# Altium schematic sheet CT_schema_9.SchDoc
size 254 x 194 mm
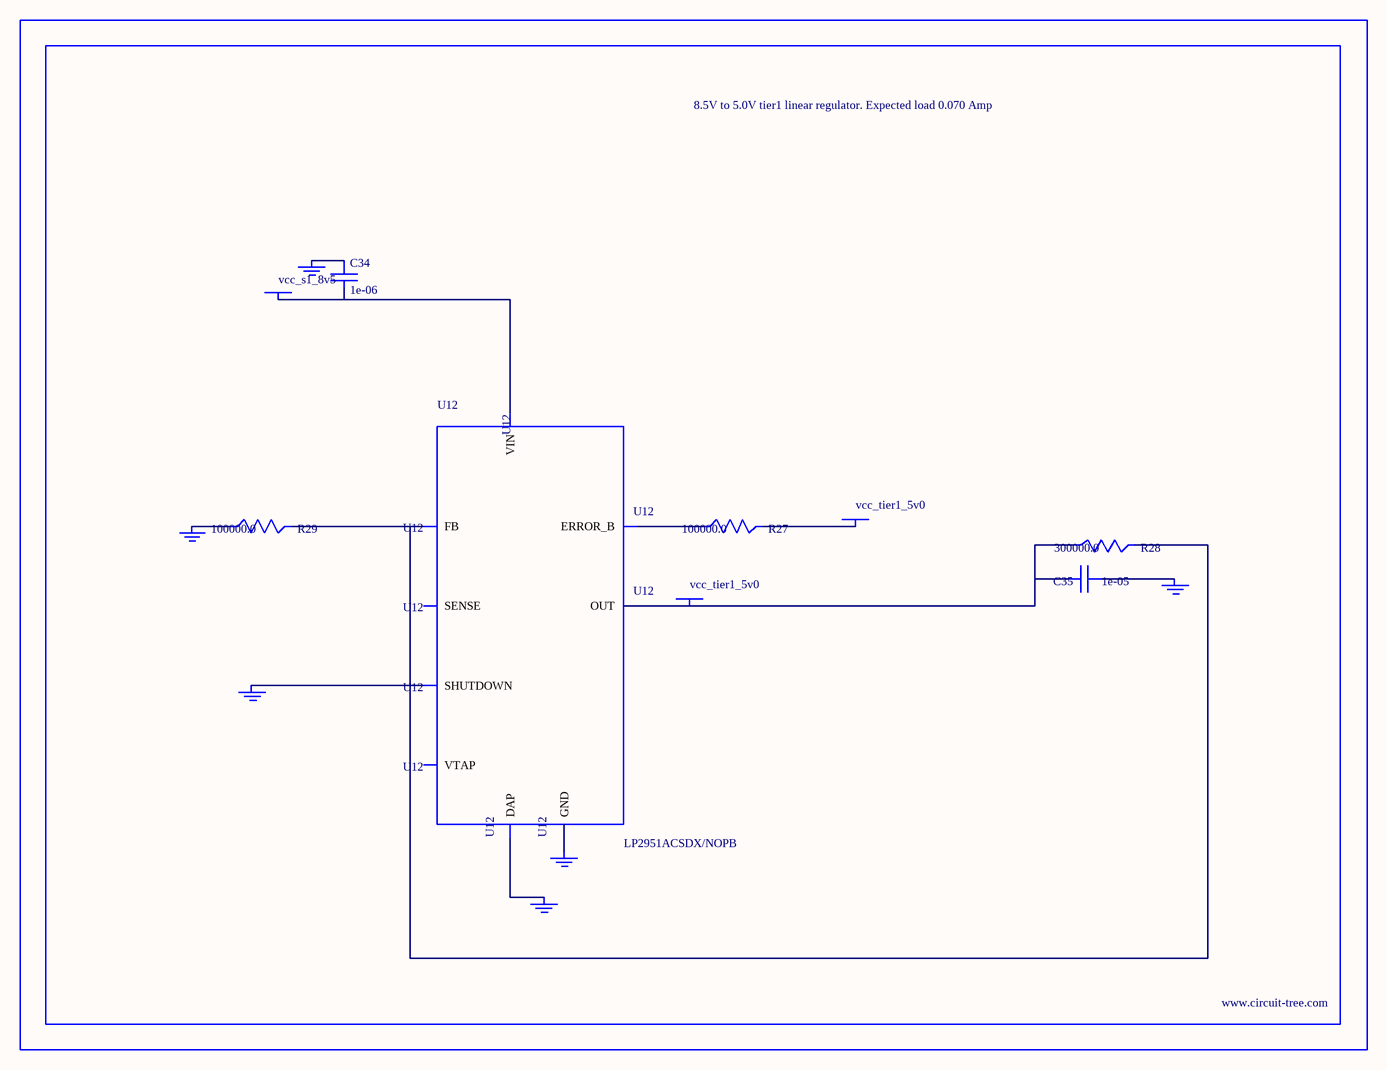
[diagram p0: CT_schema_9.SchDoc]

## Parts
BORDER8  (no value)
C34  1e-06  [C0603]
C35  1e-05  [C1210]
GND_INSTANCE_8_0  (no value)
GND_INSTANCE_8_1  (no value)
GND_INSTANCE_8_2  (no value)
GND_INSTANCE_8_3  (no value)
GND_INSTANCE_8_4  (no value)
GND_INSTANCE_8_5  (no value)
POWER_INSTANCE_8_0  vcc_tier1_5v0
POWER_INSTANCE_8_1  vcc_s1_8v5
POWER_INSTANCE_8_2  vcc_tier1_5v0
R27  100000.0  [R0603]
R28  300000.0  [R0603]
R29  100000.0  [R0603]
U12  LP2951ACSDX/NOPB  [WSON-8]

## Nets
NetC34_1: C34.1 GND_INSTANCE_8_3.0(GND)
NetC34_2: C34.2 POWER_INSTANCE_8_1.0(PWR) U12.8(VIN)
NetC35_1: C35.1 GND_INSTANCE_8_0.0(GND)
NetC35_2: C35.2 POWER_INSTANCE_8_2.0(PWR) R28.1 U12.1(OUT)
NetGND_INSTANCE_8_1_0: GND_INSTANCE_8_1.0(GND) U12.3(SHUTDOWN)
NetGND_INSTANCE_8_2_0: GND_INSTANCE_8_2.0(GND) R29.1
NetGND_INSTANCE_8_4_0: GND_INSTANCE_8_4.0(GND) U12.PAD(DAP)
NetGND_INSTANCE_8_5_0: GND_INSTANCE_8_5.0(GND) U12.4(GND)
NetPOWER_INSTANCE_8_0_0: POWER_INSTANCE_8_0.0(PWR) R27.2
NetR27_1: R27.1 U12.5(ERROR_B)
NetR28_2: R28.2 R29.2 U12.7(FB)

Not connected (* = marked no-connect by the designer): U12 2(SENSE) 6(VTAP)

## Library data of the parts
BORDER8 = BORDER_PAGE8
C34 = C0603C105K3RACTU
C35 = GRM32DR61E106MA12L
GND_INSTANCE_8_0-GND_INSTANCE_8_5 = GND
POWER_INSTANCE_8_0-POWER_INSTANCE_8_2 = PWR
R27 R29 = RC0603JR-07100KL
R28 = RC0603JR-07300KL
